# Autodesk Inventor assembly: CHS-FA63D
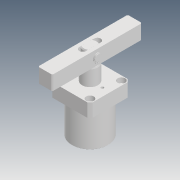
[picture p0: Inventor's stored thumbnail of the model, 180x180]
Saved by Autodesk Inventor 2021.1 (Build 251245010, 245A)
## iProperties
Created: 2019-05
Part Number: CHS-FA63D
Description: STEP AP203
Document SubType Name: Assembly
Designer: user
Title: chs-fa63d_asm.STEP
Revision Number: ÈÎºÎ
Sending System: SolidWorks 2017
Preprocessor: SwSTEP 2.0
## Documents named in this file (6)
- D:\Vault_2016\Projekty\Clamptek\Hydraulic\CHS\CHS-63\Inventor\CHS-FA63D\CHS-FA63D.iam
- D:\Vault_2016\Projekty\Clamptek\Hydraulic\CHS\CHS-63\Inventor\CHS-FA63D\CHS-FA63-03.ipt
- D:\Vault_2016\Projekty\Clamptek\Hydraulic\CHS\CHS-63\Inventor\CHS-FA63D\CHS-63D-01_1.ipt
- D:\Vault_2016\Projekty\Clamptek\Hydraulic\CHS\CHS-63\Inventor\CHS-FA63D\¿¨»É.ipt
- D:\Vault_2016\Projekty\Clamptek\Hydraulic\CHS\CHS-63\Inventor\CHS-FA63D\¶ÌÏú.ipt
- D:\Vault_2016\Projekty\Clamptek\Hydraulic\CHS\CHS-63\Inventor\CHS-FA63D\CHS-63D»îÈû¸Ë_3.ipt
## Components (6 placed, 6 different names)
1. CHS-FA63-03_1
2. CHS-63D-01_1_2
3. ¿¨»É_3
4. ¶ÌÏú_4
5. ¿¨»É_5
6. CHS-63D»îÈû¸Ë_3_6
